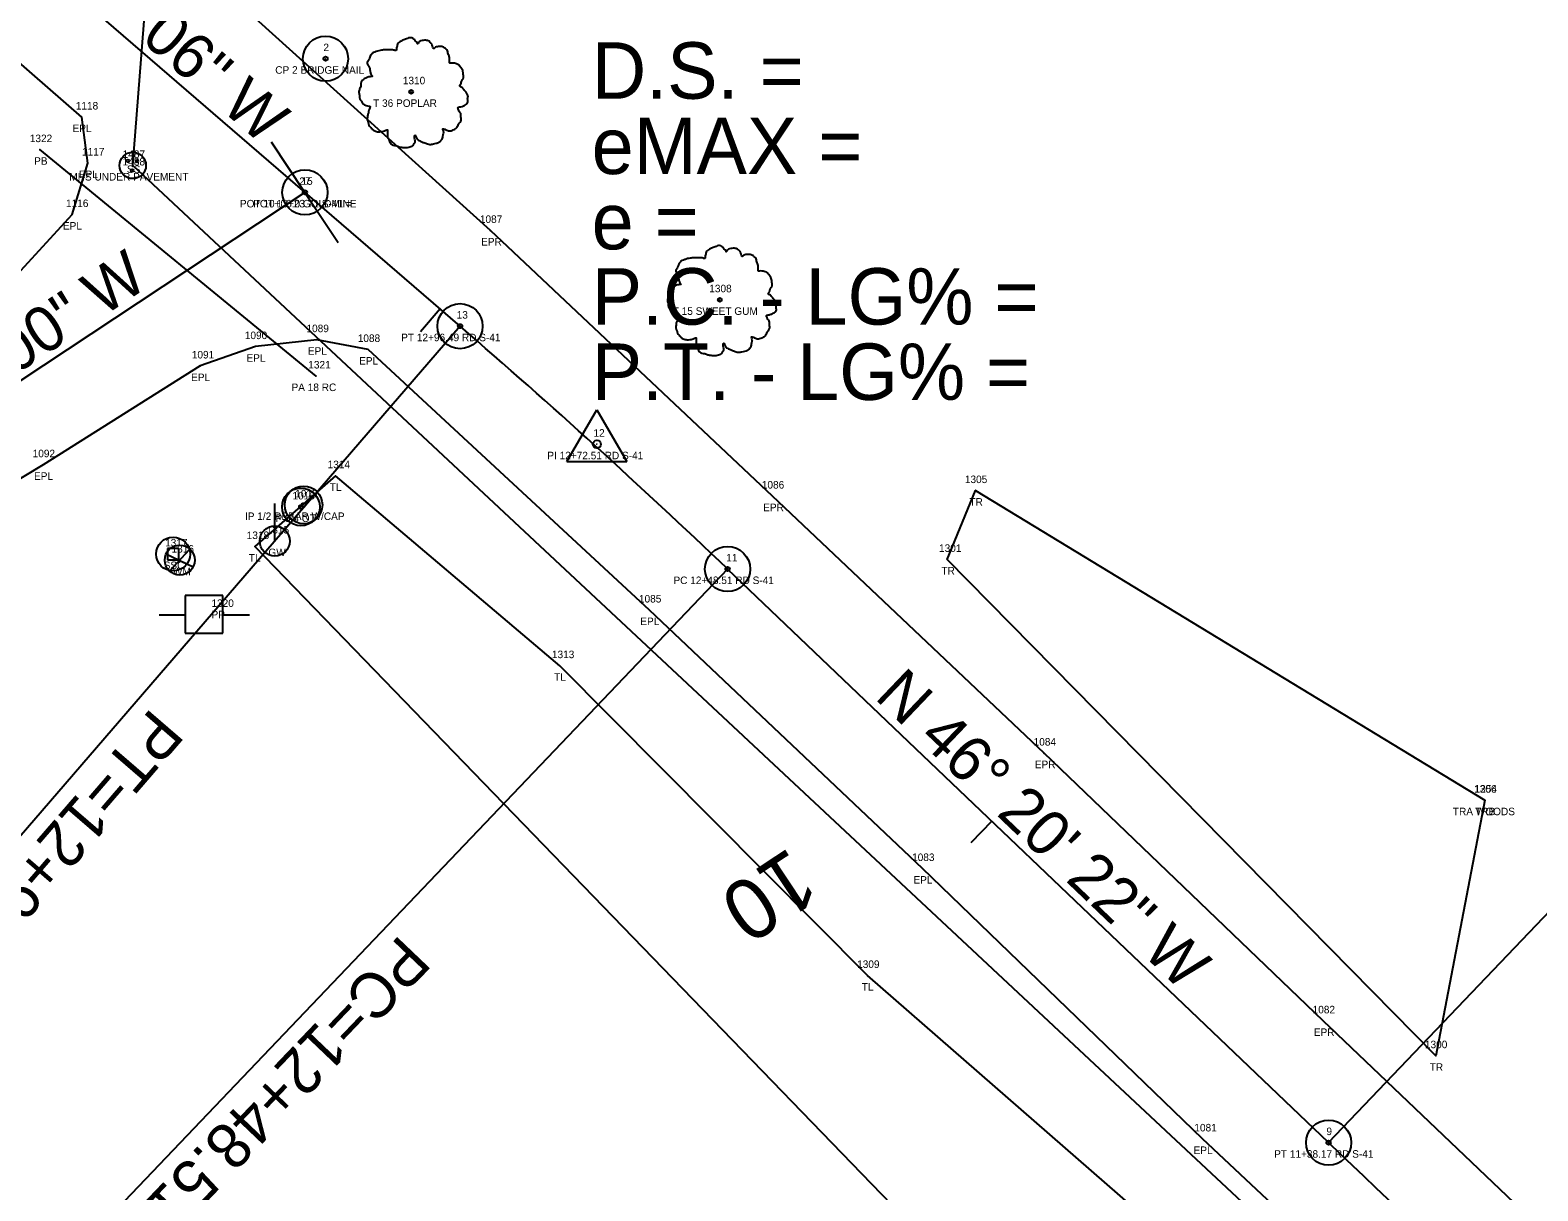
# Model space of a CAD drawing. Extents: x 1812340 to 1815011, y 1177659 to 1180159.
# Drawn here: x 1813793.4 to 1813993.7, y 1178509 to 1178663.1 of the extents above; entities that cross this region are included whole.
import ezdxf

# ---------------------------------------------------------------- set-up
doc = ezdxf.new("R2010")
doc.units = 0
for name, color, linetype in [('RD_EX_DR_Inlet', 7, 'Continuous'), ('RD_EX_DR_Pipe', 7, 'Continuous'), ('RD_EX_DR_Pipe_txCode', 7, 'Continuous'), ('RD_EX_DV_Prop_txCode', 7, 'Continuous'), ('RD_EX_DV_PropPin', 7, 'Continuous'), ('RD_EX_Road', 7, 'Continuous'), ('RD_EX_Road_txCode', 7, 'Continuous'), ('RD_EX_UT', 7, 'Continuous'), ('RD_EX_UT_txCode', 7, 'Continuous'), ('RD_EX_VEG', 7, 'Continuous'), ('RD_EX_VEG_txCode', 7, 'Continuous'), ('RD_HC_CL', 7, 'Continuous'), ('RD_HC_Data', 7, 'Continuous'), ('RD_HC_Data_Tic', 7, 'Continuous'), ('RD_HC_TX_Sta50', 7, 'Continuous'), ('RD_HC_txCode', 7, 'Continuous'), ('RD_SMD_Locator', 7, 'Continuous')]:
    doc.layers.add(name, color=color, linetype=linetype)

msp = doc.modelspace()

# ---------------------------------------------------------------- linework, layer by layer
at = {"layer": 'RD_EX_DR_Inlet'}
for centre, radius in [((1813807.05, 1178645.14), 1.75), ((1813806.38, 1178645.77), 0.175), ((1813806.96, 1178644.48), 0.175), ((1813807.61, 1178645.7), 0.175)]:
    msp.add_circle(centre, radius, dxfattribs=at)
at = {"layer": 'RD_EX_DR_Pipe'}
msp.add_line((1813831.42, 1178617.18), (1813794.72, 1178647.24), dxfattribs=at)
at = {"layer": 'RD_EX_DV_PropPin'}
for centre, radius in [((1813829.73, 1178600.06), 2.5), ((1813829.38, 1178599.79), 2.5), ((1813829.38, 1178599.79), 0.25), ((1813829.73, 1178600.06), 0.25)]:
    msp.add_circle(centre, radius, dxfattribs=at)
at = {"layer": 'RD_EX_Road'}
for points in [[(1814076.45, 1178427.4), (1814038.86, 1178461.87), (1814001.83, 1178496.62), (1813965.15, 1178531.54), (1813928.08, 1178567.1), (1813892.01, 1178601.23), (1813854.54, 1178636.51), (1813817.44, 1178670.03), (1813779.87, 1178701.64)], [(1813577.25, 1178474.27), (1813618.17, 1178504.26), (1813659.38, 1178535.26), (1813701.1, 1178565.69), (1813742.11, 1178594.54), (1813782.72, 1178623.8), (1813791.22, 1178630.12), (1813798.98, 1178638.62), (1813801.09, 1178645.46), (1813800.26, 1178651.57), (1813775.58, 1178673.13), (1813768.46, 1178675.91), (1813762.33, 1178681.89)], [(1813986.47, 1178480.85), (1813949.15, 1178515.86), (1813911.94, 1178551.77), (1813875.67, 1178586.1), (1813838.32, 1178620.7), (1813831.51, 1178622), (1813823.35, 1178621.08), (1813815.99, 1178618.51), (1813795.14, 1178605.39), (1813756.93, 1178582.36), (1813736.74, 1178567), (1813712.58, 1178549.43), (1813670.71, 1178519.43), (1813630, 1178489.55)]]:
    msp.add_lwpolyline(points, dxfattribs=at)
at = {"layer": 'RD_EX_UT'}
for p, q in [((1813825.91, 1178595.26), (1813825.91, 1178600.26)), ((1813811.45, 1178593.56), (1813815.09, 1178591.85)), ((1813813.15, 1178594.29), (1813811.65, 1178594.29)), ((1813811.65, 1178594.29), (1813811.65, 1178592.79)), ((1813811.65, 1178592.79), (1813813.15, 1178592.79)), ((1813811.94, 1178591.27), (1813814.6, 1178594.16)), ((1813813.15, 1178592.79), (1813813.15, 1178594.29)), ((1813818.99, 1178588.01), (1813813.99, 1178588.01)), ((1813813.99, 1178588.01), (1813813.99, 1178583.01)), ((1813818.99, 1178583.01), (1813818.99, 1178588.01)), ((1813810.56, 1178585.45), (1813814.03, 1178585.45)), ((1813818.92, 1178585.45), (1813822.56, 1178585.45)), ((1813813.99, 1178583.01), (1813818.99, 1178583.01))]:
    msp.add_line(p, q, dxfattribs=at)
msp.add_lwpolyline([(1814122.48, 1178351.31), (1814099.73, 1178371.68), (1813807.05, 1178645.14), (1813817.45, 1178777.9), (1813883.81, 1178790.87)], dxfattribs=at)
for centre, radius in [((1813825.91, 1178595.26), 2), ((1813812.4, 1178593.54), 2.25), ((1813813.29, 1178592.73), 2)]:
    msp.add_circle(centre, radius, dxfattribs=at)
at = {"layer": 'RD_EX_VEG'}
for points in [[(1813964.65, 1178448.48), (1813984.61, 1178463.55), (1813943.71, 1178503.46), (1813904.65, 1178537.57), (1813863.79, 1178578.71), (1813833.99, 1178603.93), (1813823.24, 1178594.53), (1813964.65, 1178448.48)], [(1813986.62, 1178560.85), (1813980.11, 1178526.91), (1813915.24, 1178592.82), (1813918.96, 1178601.96), (1813986.62, 1178560.85)]]:
    msp.add_lwpolyline(points, dxfattribs=at)
for centre, radius in [((1813844.02, 1178654.92), 0.25), ((1813844.01, 1178654.9), 0.0001), ((1813885.01, 1178627.3), 0.25), ((1813885, 1178627.28), 0.0001)]:
    msp.add_circle(centre, radius, dxfattribs=at)
for points in [[(1813844.15, 1178662.08), (1813843.85, 1178662.11), (1813843.53, 1178662.01), (1813843.28, 1178661.91), (1813843.05, 1178661.83), (1813842.83, 1178661.73), (1813842.53, 1178661.56), (1813842.3, 1178661.36), (1813842.18, 1178661.11), (1813842.13, 1178660.88), (1813842.08, 1178660.61), (1813842.08, 1178660.43), (1813841.95, 1178660.41), (1813841.8, 1178660.43), (1813841.55, 1178660.51), (1813841.3, 1178660.51), (1813841.05, 1178660.51), (1813840.7, 1178660.48), (1813840.35, 1178660.48), (1813840.08, 1178660.43), (1813839.75, 1178660.38), (1813839.38, 1178660.26), (1813839.03, 1178660.13), (1813838.73, 1178659.89), (1813838.48, 1178659.41), (1813838.35, 1178659.06), (1813838.2, 1178658.81), (1813838.35, 1178658.36), (1813838.53, 1178658.01), (1813838.55, 1178657.81), (1813838.63, 1178657.39), (1813838.73, 1178657.16), (1813838.85, 1178656.96), (1813838.78, 1178656.94), (1813838.4, 1178656.89), (1813838.1, 1178656.79), (1813837.68, 1178656.56), (1813837.45, 1178656.34), (1813837.35, 1178656.01), (1813837.33, 1178655.66), (1813837.23, 1178655.46), (1813837.15, 1178655.19), (1813837.13, 1178655.11), (1813837.08, 1178654.79), (1813837.18, 1178654.34), (1813837.2, 1178653.99), (1813837.33, 1178653.76), (1813837.48, 1178653.59), (1813837.65, 1178653.34), (1813838.05, 1178653.11), (1813838.38, 1178653.01), (1813838.58, 1178652.99), (1813838.4, 1178652.49), (1813838.35, 1178652.14), (1813838.23, 1178651.74), (1813838.23, 1178651.66), (1813838.18, 1178651.19), (1813838.33, 1178650.86), (1813838.4, 1178650.49), (1813838.58, 1178650.26), (1813838.85, 1178649.96), (1813839.18, 1178649.74), (1813839.68, 1178649.61), (1813840.08, 1178649.64), (1813840.65, 1178649.81), (1813840.9, 1178649.89), (1813840.88, 1178649.71), (1813840.9, 1178649.34), (1813840.9, 1178648.91), (1813841.05, 1178648.59), (1813841.15, 1178648.32), (1813841.3, 1178648.07), (1813841.63, 1178647.84), (1813842.03, 1178647.77), (1813842.45, 1178647.62), (1813842.9, 1178647.54), (1813843.4, 1178647.52), (1813844, 1178647.67), (1813844.27, 1178647.79), (1813844.37, 1178647.97), (1813844.57, 1178648.34), (1813844.52, 1178648.57), (1813844.55, 1178649.16), (1813844.65, 1178648.99), (1813844.82, 1178648.64), (1813845.32, 1178648.34), (1813845.72, 1178648.17), (1813846.2, 1178648.02), (1813846.5, 1178647.94), (1813846.97, 1178648.02), (1813847.35, 1178648.09), (1813847.72, 1178648.22), (1813848.02, 1178648.49), (1813848.2, 1178648.76), (1813848.25, 1178649.04), (1813848.32, 1178649.41), (1813848.37, 1178649.59)], [(1813848.37, 1178649.59), (1813848.3, 1178649.76), (1813848.25, 1178650.01), (1813848.32, 1178649.99), (1813848.5, 1178649.94), (1813848.77, 1178649.81), (1813849, 1178649.74), (1813849.32, 1178649.76), (1813849.6, 1178649.86), (1813850.05, 1178650.14), (1813850.32, 1178650.61), (1813850.6, 1178651.01), (1813850.67, 1178651.34), (1813850.62, 1178651.56), (1813850.6, 1178652.06), (1813850.4, 1178652.31), (1813850.35, 1178652.44), (1813850.25, 1178652.84), (1813850.32, 1178652.89), (1813850.6, 1178652.94), (1813850.97, 1178653.06), (1813851.25, 1178653.19), (1813851.47, 1178653.36), (1813851.55, 1178653.59), (1813851.52, 1178653.99), (1813851.57, 1178654.39), (1813851.5, 1178654.54), (1813851.4, 1178654.69), (1813851.32, 1178654.89), (1813851.17, 1178655.04), (1813851.07, 1178655.19), (1813850.97, 1178655.29), (1813850.85, 1178655.44), (1813850.67, 1178655.56), (1813850.52, 1178655.61), (1813850.47, 1178655.76), (1813850.62, 1178655.96), (1813850.67, 1178656.06), (1813850.7, 1178656.29), (1813850.92, 1178656.64), (1813850.97, 1178657.04), (1813850.92, 1178657.46), (1813850.87, 1178657.74), (1813850.72, 1178658.01), (1813850.52, 1178658.26), (1813850.4, 1178658.44), (1813850.22, 1178658.56), (1813849.9, 1178658.69), (1813849.65, 1178658.74), (1813849.3, 1178658.74), (1813849.1, 1178658.79), (1813849.12, 1178658.84), (1813849.12, 1178658.99), (1813849.12, 1178659.26), (1813849.05, 1178659.71), (1813848.9, 1178660.21), (1813848.9, 1178660.23), (1813848.8, 1178660.48), (1813848.57, 1178660.68), (1813848.4, 1178660.78), (1813848.2, 1178660.91), (1813847.95, 1178660.93), (1813847.65, 1178660.93), (1813847.37, 1178660.88), (1813847.17, 1178660.78), (1813847, 1178660.66), (1813846.92, 1178660.81), (1813846.82, 1178661.11), (1813846.77, 1178661.26), (1813846.62, 1178661.43), (1813846.4, 1178661.63), (1813845.95, 1178661.76), (1813845.32, 1178661.68), (1813845.02, 1178661.48), (1813844.87, 1178661.31), (1813844.82, 1178661.43), (1813844.62, 1178661.63), (1813844.52, 1178661.81), (1813844.35, 1178661.93), (1813844.2, 1178662.03), (1813844.1, 1178662.08)], [(1813885.14, 1178634.47), (1813884.84, 1178634.49), (1813884.52, 1178634.39), (1813884.27, 1178634.29), (1813884.04, 1178634.22), (1813883.82, 1178634.12), (1813883.52, 1178633.94), (1813883.29, 1178633.74), (1813883.17, 1178633.49), (1813883.12, 1178633.27), (1813883.07, 1178632.99), (1813883.07, 1178632.82), (1813882.94, 1178632.79), (1813882.79, 1178632.82), (1813882.54, 1178632.89), (1813882.29, 1178632.89), (1813882.04, 1178632.89), (1813881.69, 1178632.87), (1813881.34, 1178632.87), (1813881.07, 1178632.82), (1813880.74, 1178632.77), (1813880.37, 1178632.64), (1813880.02, 1178632.52), (1813879.72, 1178632.27), (1813879.47, 1178631.8), (1813879.34, 1178631.45), (1813879.19, 1178631.2), (1813879.34, 1178630.75), (1813879.52, 1178630.4), (1813879.54, 1178630.2), (1813879.62, 1178629.77), (1813879.72, 1178629.55), (1813879.84, 1178629.35), (1813879.77, 1178629.32), (1813879.39, 1178629.27), (1813879.09, 1178629.17), (1813878.67, 1178628.95), (1813878.44, 1178628.72), (1813878.34, 1178628.4), (1813878.32, 1178628.05), (1813878.22, 1178627.85), (1813878.14, 1178627.57), (1813878.12, 1178627.5), (1813878.07, 1178627.17), (1813878.17, 1178626.72), (1813878.19, 1178626.37), (1813878.32, 1178626.15), (1813878.47, 1178625.97), (1813878.64, 1178625.72), (1813879.04, 1178625.5), (1813879.37, 1178625.4), (1813879.57, 1178625.37), (1813879.39, 1178624.87), (1813879.34, 1178624.52), (1813879.22, 1178624.12), (1813879.22, 1178624.05), (1813879.17, 1178623.57), (1813879.32, 1178623.25), (1813879.39, 1178622.87), (1813879.57, 1178622.65), (1813879.84, 1178622.35), (1813880.17, 1178622.12), (1813880.67, 1178622), (1813881.07, 1178622.02), (1813881.64, 1178622.2), (1813881.89, 1178622.27), (1813881.87, 1178622.1), (1813881.89, 1178621.72), (1813881.89, 1178621.3), (1813882.04, 1178620.98), (1813882.14, 1178620.7), (1813882.29, 1178620.45), (1813882.62, 1178620.23), (1813883.02, 1178620.15), (1813883.44, 1178620), (1813883.89, 1178619.93), (1813884.39, 1178619.9), (1813884.99, 1178620.05), (1813885.27, 1178620.18), (1813885.37, 1178620.35), (1813885.57, 1178620.73), (1813885.52, 1178620.95), (1813885.54, 1178621.55), (1813885.64, 1178621.37), (1813885.82, 1178621.02), (1813886.32, 1178620.73), (1813886.72, 1178620.55), (1813887.19, 1178620.4), (1813887.49, 1178620.33), (1813887.96, 1178620.4), (1813888.34, 1178620.48), (1813888.71, 1178620.6), (1813889.01, 1178620.88), (1813889.19, 1178621.15), (1813889.24, 1178621.42), (1813889.31, 1178621.8), (1813889.36, 1178621.97)], [(1813889.36, 1178621.97), (1813889.29, 1178622.15), (1813889.24, 1178622.4), (1813889.31, 1178622.37), (1813889.49, 1178622.32), (1813889.76, 1178622.2), (1813889.99, 1178622.12), (1813890.31, 1178622.15), (1813890.59, 1178622.25), (1813891.04, 1178622.52), (1813891.31, 1178623), (1813891.59, 1178623.4), (1813891.66, 1178623.72), (1813891.61, 1178623.95), (1813891.59, 1178624.45), (1813891.39, 1178624.7), (1813891.34, 1178624.82), (1813891.24, 1178625.22), (1813891.31, 1178625.27), (1813891.59, 1178625.32), (1813891.96, 1178625.45), (1813892.24, 1178625.57), (1813892.46, 1178625.75), (1813892.54, 1178625.97), (1813892.51, 1178626.37), (1813892.56, 1178626.77), (1813892.49, 1178626.92), (1813892.39, 1178627.07), (1813892.31, 1178627.27), (1813892.16, 1178627.42), (1813892.06, 1178627.57), (1813891.96, 1178627.67), (1813891.84, 1178627.82), (1813891.66, 1178627.95), (1813891.51, 1178628), (1813891.46, 1178628.15), (1813891.61, 1178628.35), (1813891.66, 1178628.45), (1813891.69, 1178628.67), (1813891.91, 1178629.02), (1813891.96, 1178629.42), (1813891.91, 1178629.85), (1813891.86, 1178630.12), (1813891.71, 1178630.4), (1813891.51, 1178630.65), (1813891.39, 1178630.82), (1813891.21, 1178630.95), (1813890.89, 1178631.07), (1813890.64, 1178631.12), (1813890.29, 1178631.12), (1813890.09, 1178631.17), (1813890.11, 1178631.22), (1813890.11, 1178631.37), (1813890.11, 1178631.65), (1813890.04, 1178632.1), (1813889.89, 1178632.59), (1813889.89, 1178632.62), (1813889.79, 1178632.87), (1813889.56, 1178633.07), (1813889.39, 1178633.17), (1813889.19, 1178633.29), (1813888.94, 1178633.32), (1813888.64, 1178633.32), (1813888.36, 1178633.27), (1813888.16, 1178633.17), (1813887.99, 1178633.04), (1813887.91, 1178633.19), (1813887.82, 1178633.49), (1813887.77, 1178633.64), (1813887.62, 1178633.82), (1813887.39, 1178634.02), (1813886.94, 1178634.14), (1813886.32, 1178634.07), (1813886.02, 1178633.87), (1813885.87, 1178633.69), (1813885.82, 1178633.82), (1813885.62, 1178634.02), (1813885.52, 1178634.19), (1813885.34, 1178634.32), (1813885.19, 1178634.42), (1813885.09, 1178634.47)]]:
    msp.add_spline(points, degree=3, dxfattribs=at)
at = {"layer": 'RD_HC_CL'}
for p, q in [((1813850.52, 1178623.8), (1813755.38, 1178705.86)), ((1813829.91, 1178641.57), (1813743.83, 1178584.56)), ((1813965.88, 1178515.37), (1813886.05, 1178591.55))]:
    msp.add_line(p, q, dxfattribs=at)
for centre, radius, start, end in [((1813226.77, 1177900.71), 954.94, 46.33932, 49.21843), ((1817921.84, 1182660.75), 5730.08, 226.33932, 227.720866)]:
    msp.add_arc(centre, radius, start, end, dxfattribs=at)
at = {"layer": 'RD_HC_Data'}
for p, q in [((1813850.52, 1178623.8), (1813774.94, 1178536.18)), ((1813864.72, 1178605.83), (1813868.69, 1178612.71)), ((1813868.69, 1178612.71), (1813872.66, 1178605.83)), ((1813864.72, 1178605.83), (1813872.66, 1178605.83)), ((1813965.88, 1178515.37), (1814045.93, 1178599.26)), ((1813886.05, 1178591.55), (1813805.93, 1178507.6))]:
    msp.add_line(p, q, dxfattribs=at)
for centre, radius in [((1813832.65, 1178659.32), 3), ((1813832.65, 1178659.32), 0.282), ((1813829.91, 1178641.57), 3), ((1813829.91, 1178641.57), 3), ((1813829.91, 1178641.57), 0.282), ((1813829.91, 1178641.57), 0.282), ((1813850.52, 1178623.8), 3), ((1813850.52, 1178623.8), 0.282), ((1813868.69, 1178608.12), 0.529), ((1813886.05, 1178591.55), 3), ((1813886.05, 1178591.55), 0.282), ((1813965.88, 1178515.37), 3), ((1813965.88, 1178515.37), 0.282)]:
    msp.add_circle(centre, radius, dxfattribs=at)
at = {"layer": 'RD_HC_Data_Tic'}
for p, q in [((1813829.91, 1178641.57), (1813825.49, 1178648.24)), ((1813829.91, 1178641.57), (1813834.33, 1178634.9)), ((1813847.86, 1178626.09), (1813845.25, 1178623.06)), ((1813921.14, 1178558.06), (1813918.38, 1178555.17))]:
    msp.add_line(p, q, dxfattribs=at)
at = {"layer": 'RD_SMD_Locator'}
for centre in [(1813832.65, 1178659.32), (1813800.26, 1178651.57), (1813794.72, 1178647.24), (1813801.09, 1178645.46), (1813807.05, 1178645.14), (1813829.91, 1178641.57), (1813829.91, 1178641.57), (1813798.98, 1178638.62), (1813854.54, 1178636.51), (1813850.52, 1178623.8), (1813823.35, 1178621.08), (1813831.51, 1178622), (1813838.32, 1178620.7), (1813815.99, 1178618.51), (1813831.42, 1178617.18), (1813868.69, 1178608.12), (1813795.14, 1178605.39), (1813833.99, 1178603.93), (1813892.01, 1178601.23), (1813918.96, 1178601.96), (1813823.24, 1178594.53), (1813915.24, 1178592.82), (1813886.05, 1178591.55), (1813875.67, 1178586.1), (1813863.79, 1178578.71), (1813928.08, 1178567.1), (1813986.62, 1178560.85), (1813986.62, 1178560.85), (1813911.94, 1178551.77), (1813904.65, 1178537.57), (1813965.15, 1178531.54), (1813980.11, 1178526.91), (1813949.15, 1178515.86), (1813965.88, 1178515.37)]:
    msp.add_circle(centre, 0.001, dxfattribs=at)

# ---------------------------------------------------------------- texts
at = {"layer": 'RD_EX_DR_Pipe_txCode'}
for s, p in [('1322', (1813793.37, 1178648.24)), ('PB', (1813793.94, 1178645.24)), ('1321', (1813830.36, 1178618.18)), ('PA 18 RC', (1813828.13, 1178615.18))]:
    msp.add_text(s, height=1, dxfattribs=at).set_placement(p)
at = {"layer": 'RD_EX_DV_Prop_txCode'}
for s, p in [('1016', (1813828.26, 1178600.79)), ('1015', (1813828.62, 1178601.06)), ('IP 1/2 REBAR W/CAP', (1813821.95, 1178598.06)), ('IP 3/4 OT', (1813825.63, 1178597.79))]:
    msp.add_text(s, height=1, dxfattribs=at).set_placement(p)
at = {"layer": 'RD_EX_Road_txCode'}
for s, p in [('1118', (1813799.48, 1178652.57)), ('EPL', (1813799.05, 1178649.57)), ('1117', (1813800.31, 1178646.46)), ('EPL', (1813799.88, 1178643.46)), ('1116', (1813798.18, 1178639.62)), ('1087', (1813853.15, 1178637.51)), ('EPL', (1813797.77, 1178636.62)), ('EPR', (1813853.31, 1178634.51)), ('1090', (1813821.93, 1178622.08)), ('1089', (1813830.12, 1178623)), ('1088', (1813836.93, 1178621.7)), ('1091', (1813814.89, 1178619.51)), ('EPL', (1813830.3, 1178620)), ('EPL', (1813822.15, 1178619.08)), ('EPL', (1813837.11, 1178618.7)), ('EPL', (1813814.79, 1178616.51)), ('1092', (1813793.75, 1178606.39)), ('EPL', (1813793.93, 1178603.39)), ('1086', (1813890.6, 1178602.23)), ('EPR', (1813890.78, 1178599.23)), ('1085', (1813874.28, 1178587.1)), ('EPL', (1813874.46, 1178584.1)), ('1084', (1813926.7, 1178568.1)), ('EPR', (1813926.86, 1178565.1)), ('1083', (1813910.56, 1178552.77)), ('EPL', (1813910.74, 1178549.77)), ('1082', (1813963.76, 1178532.54)), ('EPR', (1813963.92, 1178529.54)), ('1081', (1813948.05, 1178516.86)), ('EPL', (1813947.95, 1178513.86))]:
    msp.add_text(s, height=1, dxfattribs=at).set_placement(p)
at = {"layer": 'RD_EX_UT_txCode'}
for s, p in [('1487', (1813805.7, 1178646.14)), ('1488', (1813805.7, 1178645.14)), ('SS', (1813806.27, 1178644.14)), ('MHS UNDER PAVEMENT', (1813798.62, 1178643.14)), ('1315', (1813824.84, 1178596.26)), ('1317', (1813811.34, 1178594.54)), ('1316', (1813812.2, 1178593.73)), ('SSC', (1813811.15, 1178591.54)), ('GW', (1813825.06, 1178593.26)), ('WM', (1813812.38, 1178590.73)), ('1320', (1813817.5, 1178586.51)), ('PP', (1813817.5, 1178585.01))]:
    msp.add_text(s, height=1, dxfattribs=at).set_placement(p)
at = {"layer": 'RD_EX_VEG_txCode'}
for s, p in [('1310', (1813842.92, 1178655.92)), ('T 36 POPLAR', (1813838.97, 1178652.92)), ('1308', (1813883.62, 1178628.3)), ('T 15 SWEET GUM', (1813878.77, 1178625.3)), ('1314', (1813832.93, 1178604.93)), ('TL', (1813833.22, 1178601.93)), ('1305', (1813917.57, 1178602.96)), ('TR', (1813918.17, 1178599.96)), ('1318', (1813822.18, 1178595.53)), ('1301', (1813914.14, 1178593.82)), ('TL', (1813822.47, 1178592.53)), ('TR', (1813914.44, 1178590.82)), ('1313', (1813862.72, 1178579.71)), ('TL', (1813863.02, 1178576.71)), ('1306', (1813985.21, 1178561.85)), ('1254', (1813985.27, 1178561.85)), ('TRA WOODS', (1813982.39, 1178558.85)), ('TRB', (1813985.35, 1178558.85)), ('1309', (1813903.26, 1178538.57)), ('TL', (1813903.88, 1178535.57)), ('1300', (1813978.68, 1178527.91)), ('TR', (1813979.31, 1178524.91))]:
    msp.add_text(s, height=1, dxfattribs=at).set_placement(p)
at = {"layer": 'RD_HC_Data'}
for s, rotation, p in [('N 49%%d 13\' 06" W', 319.2184, (1813781.4, 1178684.74)), ('S 56%%d 29\' 00" W', 33.5168, (1813762.48, 1178598.12)), ('N 46%%d 20\' 22" W', 316.3393, (1813905.44, 1178574.43)), ('PT=12+96.50', 229.2184, (1813809.57, 1178573.27)), ('PC=12+48.51', 226.3393, (1813842.62, 1178543.15))]:
    msp.add_text(s, height=6, rotation=rotation, dxfattribs=at).set_placement(p)
for s, p in [('D.S. = ', (1813868, 1178654)), ('eMAX = ', (1813868, 1178644)), ('e = ', (1813868, 1178634)), ('P.C. - LG% = ', (1813868, 1178624)), ('P.T. - LG% = ', (1813868, 1178614))]:
    msp.add_text(s, height=7.5, dxfattribs=at).set_placement(p)
at = {"layer": 'RD_HC_TX_Sta50'}
msp.add_text('10', height=8, rotation=213.5168, dxfattribs=at).set_placement((1813894.38, 1178554.73))
at = {"layer": 'RD_HC_txCode'}
for s, p in [('2', (1813832.37, 1178660.32)), ('CP 2 BRIDGE NAIL', (1813825.97, 1178657.32)), ('27', (1813829.18, 1178642.57)), ('15', (1813829.46, 1178642.57)), ('POT 10+00.0 GOLDMINE', (1813821.28, 1178639.57)), ('POT 13+23.71 S-41 =', (1813823.04, 1178639.57)), ('13', (1813850.07, 1178624.8)), ('PT 12+96.49 RD S-41', (1813842.7, 1178621.8)), ('12', (1813868.24, 1178609.12)), ('PI 12+72.51 RD S-41', (1813862.11, 1178606.12)), ('11', (1813885.88, 1178592.55)), ('PC 12+48.51 RD S-41', (1813878.86, 1178589.55)), ('9', (1813965.59, 1178516.37)), ('PT 11+38.17 RD S-41', (1813958.65, 1178513.37))]:
    msp.add_text(s, height=1, dxfattribs=at).set_placement(p)

doc.saveas('drawing.dxf')
